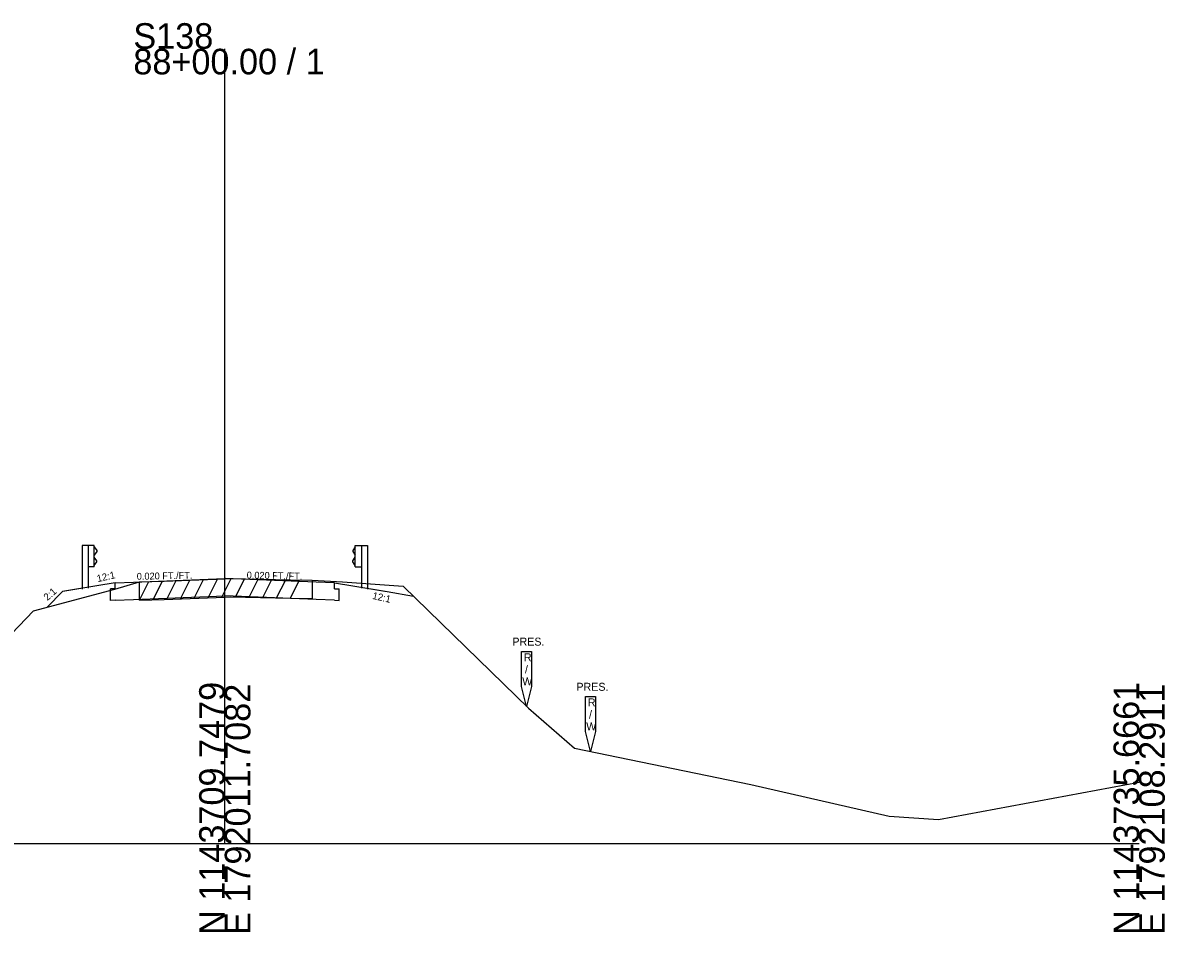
# Model space of a CAD drawing. Extents: x -26 to 1203, y -10 to 19606.
# Drawn here: x 77.9 to 202.8, y 15990.3 to 16089.8 of the extents above; entities that cross this region are included whole.
import ezdxf

# ---------------------------------------------------------------- set-up
doc = ezdxf.new("R2010")
doc.units = 0
for name, color, linetype in [('RD_EX_Driveway', 7, 'Continuous'), ('RD_GPK_XS_Cell', 7, 'Continuous'), ('RD_XS_Base', 7, 'Continuous'), ('RD_XS_EarthShd', 7, 'Continuous'), ('RD_XS_ExGround', 7, 'Continuous'), ('RD_XS_ExPaveRet', 7, 'Continuous'), ('RD_XS_ExRW', 7, 'Continuous'), ('RD_XS_GR', 7, 'Continuous'), ('RD_XS_Pave', 7, 'Continuous'), ('RD_XS_TX_Slope', 7, 'Continuous')]:
    doc.layers.add(name, color=color, linetype=linetype)

msp = doc.modelspace()

# ---------------------------------------------------------------- linework, layer by layer
at = {"layer": 'RD_GPK_XS_Cell'}
for p, q in [((100, 16000), (100, 16086.94)), ((0, 16000), (100, 16000)), ((100, 16000), (200, 16000))]:
    msp.add_line(p, q, dxfattribs=at)
at = {"layer": 'RD_XS_Base'}
for p, q in [((88, 16027.88), (87.5, 16027.86)), ((87.5, 16026.59), (87.5, 16027.86)), ((88, 16027.88), (88, 16028.51)), ((112, 16027.88), (112, 16028.51)), ((112, 16027.88), (112.5, 16027.86)), ((112.5, 16026.59), (112.5, 16027.86)), ((88, 16026.61), (87.5, 16026.59)), ((88, 16026.61), (90, 16026.69)), ((90, 16026.69), (100, 16027.11)), ((110, 16026.69), (100, 16027.11)), ((112, 16026.61), (110, 16026.69)), ((112, 16026.61), (112.5, 16026.59))]:
    msp.add_line(p, q, dxfattribs=at)
at = {"layer": 'RD_XS_EarthShd'}
for p, q in [((86, 16028.18), (82.25, 16027.56)), ((86, 16028.18), (82.5, 16027.6)), ((88, 16028.51), (86, 16028.18)), ((112, 16028.51), (114, 16028.18)), ((114, 16028.18), (117.5, 16027.6)), ((114, 16028.18), (117.75, 16027.56)), ((80.56, 16025.86), (82.25, 16027.56)), ((117.75, 16027.56), (120.64, 16027.07))]:
    msp.add_line(p, q, dxfattribs=at)
at = {"layer": 'RD_XS_ExGround'}
msp.add_lwpolyline([(0, 16001.59), (21.73, 16004.08), (44, 16004.68), (59.36, 16005.36), (65.49, 16011.27), (79.07, 16025.47), (87.96, 16027.83), (90.67, 16028.63), (93.37, 16028.71), (100, 16028.95), (100.64, 16028.98), (107.17, 16028.85), (109.54, 16028.82), (112.86, 16028.64), (119.52, 16028.17), (133.2, 16014.81), (138.25, 16010.43), (157.53, 16006.46), (172.64, 16002.99), (178.06, 16002.63), (200, 16006.73)], dxfattribs=at)
at = {"layer": 'RD_XS_ExPaveRet'}
for p, q in [((98.17, 16026.89), (99.19, 16028.92)), ((99.67, 16026.94), (100.69, 16028.98)), ((101.17, 16026.97), (102.16, 16028.95)), ((102.67, 16026.94), (103.66, 16028.92)), ((90.67, 16026.63), (91.68, 16028.66)), ((90.67, 16026.63), (90.67, 16028.63)), ((92.17, 16026.68), (93.18, 16028.7)), ((93.67, 16026.72), (94.69, 16028.76)), ((95.17, 16026.78), (96.19, 16028.81)), ((96.67, 16026.83), (97.69, 16028.87)), ((104.17, 16026.91), (105.16, 16028.89)), ((105.67, 16026.88), (106.66, 16028.86)), ((107.17, 16026.85), (108.16, 16028.84)), ((109.54, 16028.82), (109.54, 16026.82)), ((90.67, 16026.63), (93.37, 16026.71)), ((93.37, 16026.71), (100, 16026.95)), ((100, 16026.95), (100.64, 16026.98)), ((100.64, 16026.98), (107.17, 16026.85)), ((107.17, 16026.85), (109.54, 16026.82))]:
    msp.add_line(p, q, dxfattribs=at)
at = {"layer": 'RD_XS_ExRW'}
for points in [[(132.45, 16021.02), (133.55, 16021.02), (133.55, 16017.19), (133, 16015.01), (132.45, 16017.19)], [(139.45, 16016.09), (140.55, 16016.09), (140.55, 16012.26), (140, 16010.07), (139.45, 16012.26)]]:
    msp.add_lwpolyline(points, close=True, dxfattribs=at)
at = {"layer": 'RD_XS_GR'}
for p, q in [((84.4, 16032.6), (84.4, 16027.83)), ((85.06, 16032.6), (84.4, 16032.6)), ((85.06, 16032.6), (85.06, 16027.94)), ((85.73, 16032.6), (85.06, 16032.6)), ((85.73, 16030.26), (85.73, 16032.6)), ((85.73, 16032.45), (86, 16032.05)), ((86, 16031.95), (85.73, 16031.55)), ((86, 16032.05), (86, 16031.95)), ((114.27, 16032.45), (114, 16032.05)), ((114, 16032.05), (114, 16031.95)), ((114, 16031.95), (114.27, 16031.55)), ((114.27, 16030.26), (114.27, 16032.6)), ((114.27, 16032.6), (114.94, 16032.6)), ((114.94, 16032.6), (114.94, 16027.94)), ((114.94, 16032.6), (115.6, 16032.6)), ((115.6, 16032.6), (115.6, 16027.83)), ((85.73, 16030.26), (85.06, 16030.26)), ((86, 16030.91), (85.73, 16031.31)), ((85.73, 16030.41), (86, 16030.81)), ((86, 16030.81), (86, 16030.91)), ((114, 16030.91), (114.27, 16031.31)), ((114, 16030.81), (114, 16030.91)), ((114.27, 16030.41), (114, 16030.81)), ((114.27, 16030.26), (114.94, 16030.26))]:
    msp.add_line(p, q, dxfattribs=at)
at = {"layer": 'RD_XS_Pave'}
for p, q in [((90, 16028.6), (100, 16029.01)), ((110, 16028.6), (100, 16029.01)), ((88, 16028.51), (90, 16028.6)), ((112, 16028.51), (110, 16028.6))]:
    msp.add_line(p, q, dxfattribs=at)

# ---------------------------------------------------------------- texts
at = {"layer": 'RD_EX_Driveway'}
msp.add_text('541.48', height=0.0975, rotation=90, dxfattribs=at).set_placement((100.1, 16028.95))
at = {"layer": 'RD_GPK_XS_Cell'}
for s, p in [('S138', (90, 16086.94)), ('88+00.00 / 1', (90, 16084.14))]:
    msp.add_text(s, height=2.8, dxfattribs=at).set_placement(p)
for s, p in [('N 1143709.7479', (100, 15990)), ('E 1792011.7082', (102.8, 15990)), ('N 1143735.6661', (200, 15990)), ('E 1792108.2911', (202.8, 15990))]:
    msp.add_text(s, height=2.8, rotation=90, dxfattribs=at).set_placement(p)
at = {"layer": 'RD_XS_ExRW'}
for s, p in [('PRES.', (131.45, 16021.65)), ('R', (132.71, 16019.93)), ('/', (132.83, 16018.62)), ('W', (132.53, 16017.31)), ('PRES.', (138.45, 16016.71)), ('R', (139.71, 16015)), ('/', (139.83, 16013.68)), ('W', (139.53, 16012.37))]:
    msp.add_text(s, height=0.875, dxfattribs=at).set_placement(p)
at = {"layer": 'RD_XS_TX_Slope'}
for s, height, rotation, p in [('12:1', 0.778, 12.7511, (86.1, 16028.59)), ('0.020 FT./FT.', 0.7518, 1.1916, (90.38, 16028.85)), ('0.020 FT./FT.', 0.7518, 358.8084, (102.39, 16029)), ('2:1', 0.778, 40.6589, (80.59, 16026.52)), ('12:1', 0.778, 347.2489, (116.09, 16026.77))]:
    msp.add_text(s, height=height, rotation=rotation, dxfattribs=at).set_placement(p)

doc.saveas('drawing.dxf')
